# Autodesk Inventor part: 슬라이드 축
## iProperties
Company: 한국ATC센터
Created: 2014-07
Part Number: 슬라이드 축
Document SubType Name: 모델링
Designer: KYOUNG IL JANG
Mass: 19.8501 g
Surface Area: 63.0734 cm^2
Volume: 19.8501 cm^3
Density: 1 g/cm^3
변환 표준: STEP AP214IS
파일 이름: C:\Users\SeoGD\Desktop\?쒗뿕\異?stp
전처리기: Build: 253, Release: 2010 SP1 - Date: Wed 07/29/2009
전송 단위: 밀리미터
불확실성: 0.01
Author: KYOUNG IL JANG
